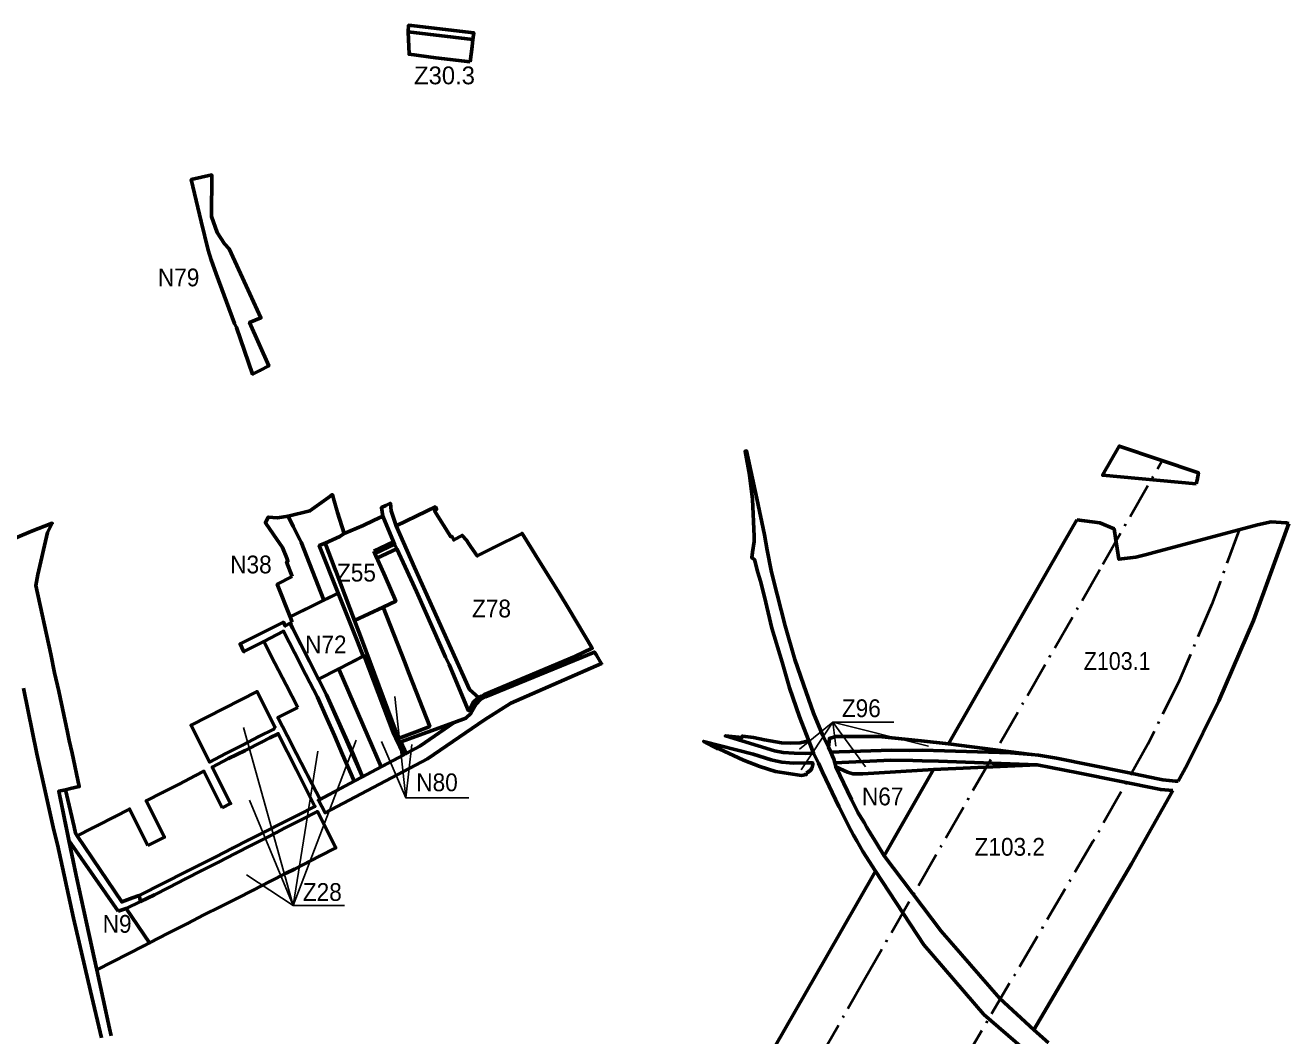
# Model space of a CAD drawing. Extents: x -650277 to -643420, y -1073980 to -1066720.
# Drawn here: x -648765 to -647061, y -1068122 to -1066758 of the extents above; entities that cross this region are included whole.
import ezdxf

# ---------------------------------------------------------------- set-up
doc = ezdxf.new("R2010")
doc.units = 0
doc.header["$LTSCALE"] = 9.6
doc.linetypes.add('DOT_DASHED', pattern=[7.7, 5, -1.2, 0.3, -1.2])
for name, color, linetype, lineweight in [('1', 7, 'Continuous', 60), ('15', 7, 'Continuous', 60), ('3', 7, 'Continuous', 60), ('40', 7, 'Continuous', 60), ('42', 7, 'Continuous', 60), ('45', 7, 'Continuous', 60), ('48', 7, 'Continuous', 60), ('60', 7, 'Continuous', 60), ('61', 7, 'Continuous', 60), ('62', 7, 'DOT_DASHED', 40), ('63', 7, 'Continuous', 25), ('7', 7, 'Continuous', 60), ('9', 7, 'Continuous', 60)]:
    doc.layers.add(name, color=color, linetype=linetype, lineweight=lineweight)

msp = doc.modelspace()

# ---------------------------------------------------------------- linework, layer by layer
at = {"layer": '1'}
msp.add_line((-648609.91, -1067940.58), (-648611.61, -1067932.63), dxfattribs=at)
for points in [[(-648397.98, -1067678.79), (-648424.69, -1067692.54), (-648412.19, -1067716.82), (-648399.58, -1067741.31), (-648387.04, -1067765.67), (-648384.25, -1067771.07), (-648367.811, -1067802.994), (-648321.623, -1067778.399), (-648326, -1067769), (-648337.32, -1067742.59), (-648348.55, -1067716.71), (-648359.6, -1067691.58), (-648371.34, -1067665.08), (-648386.91, -1067634.83), (-648402.02, -1067605.49), (-648417.12, -1067576.17), (-648443.83, -1067589.92), (-648428.7, -1067619.24), (-648413.57, -1067648.57)], [(-648342.697, -1067626.806), (-648369.949, -1067640.851), (-648359.213, -1067661.956), (-648310.511, -1067772.476), (-648285.254, -1067759.008), (-648296.891, -1067732.172), (-648342.023, -1067628.096)], [(-648519.63, -1067691.58), (-648541.86, -1067702.86), (-648516.73, -1067752.57), (-648494.84, -1067741.06), (-648472.5, -1067729.76), (-648450.23, -1067718.32), (-648430.17, -1067708.33), (-648428.67, -1067705.52), (-648452.72, -1067657.62)]]:
    msp.add_lwpolyline(points, close=True, dxfattribs=at)
for points in [[(-648399.64, -1067763.26), (-648424.14, -1067714.34), (-648435.34, -1067720.01), (-648446.58, -1067725.71), (-648468.97, -1067736.91), (-648480.06, -1067742.47), (-648491.14, -1067748.02), (-648513.23, -1067759.38), (-648488.49, -1067808.76), (-648499.7, -1067814.37)], [(-648611.61, -1067932.63), (-648547.09, -1067899.87), (-648530.81, -1067891.61), (-648508.22, -1067880.38), (-648486.09, -1067868.98), (-648463.91, -1067857.74), (-648441.47, -1067846.37), (-648419.44, -1067835.3), (-648397.04, -1067823.85), (-648374.84, -1067812.43), (-648399.64, -1067763.26)], [(-648499.7, -1067814.37), (-648524.44, -1067765.11), (-648535.61, -1067770.85), (-648557.84, -1067782.26), (-648580.14, -1067793.61), (-648602.3, -1067804.83), (-648577.78, -1067854.07), (-648600.14, -1067865.29)], [(-648600.14, -1067865.29), (-648624.76, -1067816.11), (-648645.11, -1067826.48), (-648668.085, -1067838.186), (-648675.26, -1067841.84), (-648695.27, -1067852.04), (-648664.41, -1067897.91)], [(-648572.5, -1067983.59), (-648546.76, -1067970.44), (-648524.72, -1067958.93), (-648502.59, -1067948), (-648480.12, -1067936.55), (-648457.87, -1067925.4), (-648435.55, -1067913.84), (-648413.41, -1067902.53), (-648402.29, -1067897.02), (-648391.08, -1067891.24), (-648368.78, -1067879.75), (-648346.57, -1067868.56), (-648371.27, -1067819.47), (-648393.35, -1067830.81), (-648415.69, -1067841.98), (-648426.65, -1067847.64), (-648437.89, -1067853.4), (-648460.33, -1067864.88), (-648482.5, -1067876.22), (-648504.92, -1067887.52), (-648527.33, -1067898.74), (-648549.44, -1067910.07), (-648571.88, -1067921.71), (-648591.04, -1067931.62), (-648609.91, -1067940.58)], [(-648664.41, -1067897.91), (-648635.249, -1067941.252), (-648620.658, -1067935.93), (-648611.61, -1067932.63)], [(-648609.91, -1067940.58), (-648629.22, -1067950.214), (-648597.93, -1067996.72), (-648572.5, -1067983.59)]]:
    msp.add_lwpolyline(points, dxfattribs=at)
at = {"layer": '15'}
msp.add_line((-648264.34, -1067464.83), (-648267.21, -1067458.61), dxfattribs=at)
for points in [[(-648161.58, -1066777.41), (-648160.51, -1066768.4), (-648248.43, -1066758.34), (-648248.77, -1066767.43)], [(-648362.585, -1067534.204), (-648343.41, -1067524.81), (-648369.01, -1067460.52), (-648361, -1067457.36), (-648341.15, -1067448.14), (-648335.38, -1067444.07), (-648344.41, -1067416.04), (-648349.67, -1067396.88), (-648351.06, -1067391.62), (-648352.16, -1067392.42), (-648353.35, -1067393.29), (-648381.48, -1067413.68), (-648410.92, -1067420.63), (-648409.61, -1067423.44), (-648404.29, -1067434.9), (-648394.92, -1067452.23), (-648393.17, -1067455.88)], [(-648237.81, -1067522.42), (-648204.88, -1067596.54), (-648198.39, -1067610.97), (-648193.8, -1067621), (-648189.03, -1067631.71), (-648167.48, -1067683.45), (-648164.79, -1067678.96), (-648163.11, -1067676.17), (-648160.68, -1067671.55), (-648153.98, -1067665.43), (-648166.173, -1067654.853), (-648240.51, -1067489.9), (-648265.197, -1067434.03), (-648265.197, -1067434.03), (-648272.022, -1067413.59), (-648273.008, -1067403.338), (-648279.24, -1067406.38), (-648285.08, -1067409.24), (-648283.21, -1067420.88), (-648268.67, -1067455.43), (-648267.21, -1067458.61), (-648294.04, -1067471.35), (-648291.172, -1067477.571), (-648264.34, -1067464.83), (-648253.1, -1067489.23)], [(-648359.6, -1067691.58), (-648348.55, -1067716.71), (-648337.32, -1067742.59), (-648326, -1067769), (-648321.623, -1067778.399), (-648310.511, -1067772.476), (-648323.178, -1067741.953), (-648359.213, -1067661.956), (-648405.054, -1067571.837), (-648408.002, -1067565.219), (-648414.73, -1067568.8), (-648417.19, -1067564.02), (-648475.78, -1067593.11), (-648473.34, -1067598.06), (-648470.57, -1067603.69), (-648470.47, -1067603.64), (-648443.83, -1067589.92), (-648417.12, -1067576.17), (-648402.02, -1067605.49), (-648386.91, -1067634.83), (-648371.34, -1067665.08)], [(-647988.235, -1067619.912), (-647995.04, -1067608.56), (-647997.68, -1067604.11), (-648144.83, -1067664.48), (-648151.6, -1067668.12), (-648157.2, -1067674.32), (-648161, -1067680.96), (-648162.69, -1067684), (-648164.09, -1067686.51), (-648171.21, -1067693.37), (-648187.139, -1067699.179), (-648233.264, -1067731.288), (-648251.711, -1067741.124), (-648258.96, -1067725.37), (-648262.632, -1067726.711), (-648255.016, -1067742.886), (-648319.983, -1067777.526), (-648370.113, -1067804.22), (-648360.993, -1067821.027), (-648222.872, -1067748.412), (-648146.127, -1067695.8), (-648110.36, -1067673.133), (-647988.052, -1067619.624)]]:
    msp.add_lwpolyline(points, close=True, dxfattribs=at)
for points in [[(-648793.71, -1067456.88), (-648757.97, -1067441.51), (-648728.95, -1067430.33), (-648735.59, -1067442.88), (-648748.53, -1067499.3), (-648751.29, -1067514.57), (-648731.06, -1067607.06), (-648725.8, -1067632.36), (-648720.1, -1067657.12), (-648708.26, -1067712.07), (-648706.08, -1067723.56), (-648702.33, -1067740.84), (-648692.53, -1067785.79), (-648704.614, -1067788.491), (-648710.961, -1067789.906), (-648720.34, -1067792), (-648696.93, -1067905.76), (-648672.31, -1068017.25), (-648668.92, -1068032.96), (-648651.89, -1068111.95), (-648649.74, -1068121.95)], [(-648267.21, -1067458.61), (-648294.04, -1067471.35), (-648291.172, -1067477.571), (-648264.34, -1067464.83)], [(-648662.71, -1068124.76), (-648677.61, -1068061.74), (-648700.16, -1067963.42), (-648722.09, -1067863.84), (-648727.05, -1067844.33), (-648738.7, -1067792.04), (-648749.97, -1067741.49), (-648767.84, -1067652.98)], [(-648710.961, -1067789.906), (-648720.34, -1067792), (-648706.687, -1067858.345), (-648640, -1067954)], [(-648695.27, -1067852.04), (-648697.7, -1067848.43), (-648699.621, -1067840.06), (-648699.593, -1067840.046), (-648710.96, -1067789.91)], [(-648611.61, -1067932.63), (-648620.658, -1067935.93), (-648635.249, -1067941.252), (-648664.41, -1067897.91), (-648695.27, -1067852.04)], [(-648640, -1067954), (-648629.22, -1067950.214), (-648609.91, -1067940.58), (-648611.61, -1067932.63)]]:
    msp.add_lwpolyline(points, dxfattribs=at)
at = {"layer": '3'}
msp.add_lwpolyline([(-648165.33, -1066807.74), (-648162.8, -1066786.8), (-648161.58, -1066777.41), (-648248.77, -1066767.43), (-648247.78, -1066797.53), (-648211.58, -1066802.18)], close=True, dxfattribs=at)
at = {"layer": '40'}
msp.add_lwpolyline([(-648405.27, -1067502.27), (-648425.5, -1067512.73), (-648408.26, -1067556.58), (-648362.585, -1067534.205), (-648393.17, -1067455.88), (-648394.92, -1067452.23), (-648404.29, -1067434.9), (-648410.92, -1067420.63), (-648425, -1067423.05), (-648437.75, -1067421.99), (-648441.48, -1067429.63), (-648430.4, -1067445.51), (-648418.3, -1067462.86), (-648412.46, -1067477.42), (-648411.25, -1067481.73), (-648412.89, -1067482.55)], close=True, dxfattribs=at)
at = {"layer": '42'}
msp.add_lwpolyline([(-647606.818, -1067879.061), (-647540.208, -1067762.876), (-647635.758, -1067768.38), (-647649.22, -1067768.38), (-647656.469, -1067766.309), (-647672.05, -1067758.98), (-647650.8, -1067803.28), (-647642.29, -1067820.76), (-647637.21, -1067829.29), (-647633.69, -1067834.31), (-647630.3, -1067841.02), (-647625.37, -1067848.86), (-647617.25, -1067861.95)], close=True, dxfattribs=at)
at = {"layer": '45'}
msp.add_lwpolyline([(-648405.41, -1067563.84), (-648408.002, -1067565.219), (-648369.949, -1067640.851), (-648342.697, -1067626.806), (-648328.54, -1067619.51), (-648309.522, -1067609.713), (-648317.43, -1067590), (-648343.41, -1067524.81), (-648408.26, -1067556.58)], close=True, dxfattribs=at)
at = {"layer": '48'}
for points in [[(-648528.01, -1067023.13), (-648518.72, -1067061.99), (-648514.86, -1067074.83), (-648507.88, -1067093.9), (-648483.31, -1067160.63), (-648480.57, -1067166.13), (-648458.73, -1067229.1), (-648449.03, -1067224.14), (-648437.02, -1067217.99), (-648462.97, -1067159.24), (-648447.66, -1067153.25), (-648467.56, -1067110.02), (-648490.23, -1067060.06), (-648496.87, -1067053.5), (-648506.78, -1067037.81), (-648514.38, -1067016.2), (-648513.842, -1066960.243), (-648541.52, -1066966.657)], [(-648342.023, -1067628.096), (-648296.891, -1067732.172), (-648285.254, -1067759.008), (-648255.016, -1067742.886), (-648265.614, -1067720.378), (-648269.27, -1067712.6), (-648308.43, -1067609.15), (-648328.54, -1067619.51), (-648342.697, -1067626.806)], [(-648258.96, -1067725.37), (-648251.711, -1067741.124), (-648233.264, -1067731.288), (-648187.139, -1067699.179)]]:
    msp.add_lwpolyline(points, close=True, dxfattribs=at)
for points in [[(-648265.08, -1067712.06), (-648261.25, -1067720.39), (-648235.78, -1067710.79), (-648219.86, -1067704.42), (-648247.53, -1067633.53), (-648254.04, -1067616.96), (-648282.863, -1067543.596), (-648321.36, -1067561.69)], [(-648321.361, -1067561.69), (-648311.95, -1067586.45), (-648265.08, -1067712.06)]]:
    msp.add_lwpolyline(points, dxfattribs=at)
at = {"layer": '60'}
for points in [[(-647606.818, -1067879.061), (-647617.25, -1067861.95), (-647625.37, -1067848.86), (-647630.3, -1067841.02), (-647633.69, -1067834.31), (-647637.21, -1067829.29), (-647642.29, -1067820.76), (-647650.8, -1067803.28), (-647672.05, -1067758.98), (-647673.47, -1067753.48), (-647673.47, -1067753.48), (-647674.67, -1067748.73), (-647676.47, -1067744.5), (-647678.66, -1067739.38), (-647681.91, -1067732.74), (-647690.09, -1067716.05), (-647702.04, -1067686.86), (-647715.92, -1067648.12), (-647727.37, -1067614.33), (-647740.49, -1067568.67), (-647751.41, -1067526.58), (-647756.55, -1067505.32), (-647759.16, -1067494.01), (-647764.89, -1067466.64), (-647768.5, -1067446.04), (-647778.78, -1067397.1), (-647792.52, -1067332.74), (-647794.54, -1067333.14), (-647788.77, -1067365.03), (-647784.55, -1067398.01), (-647782.39, -1067448.34), (-647782.5, -1067455.11), (-647784.36, -1067469.6), (-647785.64, -1067477.02), (-647781.85, -1067479.19), (-647777.55, -1067496.95), (-647773.96, -1067508.48), (-647768.5, -1067529.75), (-647758.25, -1067571.79), (-647744.61, -1067617.96), (-647734.63, -1067652.57), (-647721.05, -1067691.73), (-647708.71, -1067723.99), (-647702.21, -1067740.43), (-647699.89, -1067745.24), (-647697.85, -1067749.46), (-647695.71, -1067753.9), (-647690.19, -1067766.37), (-647668.13, -1067812.76), (-647651.94, -1067844.36), (-647648.33, -1067851.17), (-647643.83, -1067859.13), (-647635.77, -1067873.43), (-647618.773, -1067899.914)], [(-647783.54, -1067742.11), (-647850.45, -1067724.77), (-647838.18, -1067731.62), (-647832.56, -1067734.22), (-647829.49, -1067734.58), (-647796.87, -1067750.25), (-647774.54, -1067758.68), (-647753.53, -1067765.58), (-647718.54, -1067770.6), (-647712.01, -1067769.63), (-647712.26, -1067767.28)], [(-647712.26, -1067767.28), (-647711.773, -1067767.135), (-647711.286, -1067766.968), (-647710.799, -1067766.777), (-647710.315, -1067766.562), (-647709.834, -1067766.324), (-647709.359, -1067766.062), (-647708.892, -1067765.776), (-647708.433, -1067765.466), (-647707.985, -1067765.133), (-647707.55, -1067764.777), (-647707.128, -1067764.398), (-647706.723, -1067763.999), (-647706.335, -1067763.579), (-647705.966, -1067763.14), (-647705.617, -1067762.683), (-647705.29, -1067762.21), (-647704.985, -1067761.721), (-647704.704, -1067761.22), (-647704.447, -1067760.707), (-647704.216, -1067760.184), (-647704.01, -1067759.653), (-647703.83, -1067759.117), (-647703.675, -1067758.576), (-647703.547, -1067758.033), (-647703.445, -1067757.489), (-647703.368, -1067756.946), (-647703.315, -1067756.406), (-647703.287, -1067755.87), (-647703.282, -1067755.341), (-647703.3, -1067754.818), (-647703.34, -1067754.304), (-647703.4, -1067753.8), (-647711.09, -1067753.71), (-647728.98, -1067754.07), (-647734.69, -1067753.66), (-647744.74, -1067752.93), (-647757.74, -1067749.96), (-647759.13, -1067749.54), (-647783.54, -1067742.11)], [(-647405.026, -1068113.904), (-647451.024, -1068071.886), (-647530.038, -1067980.839), (-647606.818, -1067879.061)], [(-647618.773, -1067899.914), (-647553.628, -1067999.427), (-647472.338, -1068093.096), (-647419.713, -1068138.871)], [(-647385.13, -1068131.51), (-647405.026, -1068113.904)]]:
    msp.add_lwpolyline(points, dxfattribs=at)
for points in [[(-647754.88, -1067737.59), (-647743.12, -1067739.93), (-647728.29, -1067740.64), (-647713.15, -1067741), (-647702.21, -1067740.43), (-647708.71, -1067723.99), (-647720.45, -1067726.49), (-647732.71, -1067727.02), (-647745.41, -1067726.6), (-647768.53, -1067722.82), (-647783.13, -1067719.68), (-647798.17, -1067717.58), (-647798.5, -1067719.67), (-647821.02, -1067717.33)], [(-647596.91, -1067736.61), (-647572.33, -1067737.03), (-647555.58, -1067736.71), (-647525.685, -1067737.542), (-647436.72, -1067740.02), (-647408.2, -1067742.37), (-647520.145, -1067727.879), (-647557, -1067724), (-647614, -1067718), (-647643, -1067718), (-647672, -1067718), (-647680.804, -1067720.745), (-647681.91, -1067732.74), (-647678.66, -1067739.38), (-647678.66, -1067739.38), (-647667.76, -1067739.01), (-647638.75, -1067738.03)], [(-647540.208, -1067762.876), (-647400.63, -1067756.19), (-647533.597, -1067751.344), (-647555.67, -1067750.91), (-647568.36, -1067750.7), (-647597.83, -1067750.21), (-647673.47, -1067753.48), (-647672.05, -1067758.98), (-647672.05, -1067758.98), (-647656.469, -1067766.309), (-647649.22, -1067768.38), (-647635.758, -1067768.38)]]:
    msp.add_lwpolyline(points, close=True, dxfattribs=at)
at = {"layer": '61'}
msp.add_lwpolyline([(-647185.93, -1067377.38), (-647184.97, -1067372.22), (-647183.09, -1067362.16), (-647289.924, -1067326.309), (-647312.383, -1067365.484)], close=True, dxfattribs=at)
for points in [[(-647346.944, -1067425.768), (-647364.024, -1067455.561), (-647520.145, -1067727.879), (-647408.2, -1067742.37), (-647398.74, -1067743.15), (-647374.55, -1067747.34)], [(-647243.39, -1067469.81), (-647252.99, -1067472.35), (-647267.49, -1067476.23), (-647290.23, -1067478.89), (-647292.51, -1067464.56), (-647294.31, -1067453.26), (-647296.75, -1067437.91), (-647315.89, -1067429.71), (-647346.944, -1067425.768)], [(-647061.252, -1067430.908), (-647063.45, -1067430.19), (-647064.87, -1067429.73), (-647084.77, -1067428.64), (-647103.55, -1067432.54), (-647243.39, -1067469.81)], [(-647210.537, -1067778.594), (-647198.088, -1067756.5), (-647155.592, -1067670.17), (-647108.971, -1067561.55), (-647061.252, -1067430.908)], [(-647374.55, -1067747.34), (-647280.78, -1067766.44), (-647237.91, -1067775.18), (-647231.17, -1067776.55), (-647213.92, -1067778.26), (-647210.537, -1067778.594)], [(-647400.63, -1067756.19), (-647540.208, -1067762.876), (-647593.267, -1067855.425), (-647606.818, -1067879.061)], [(-647217.611, -1067791.149), (-647233.83, -1067789.69), (-647345.11, -1067767.28), (-647400.63, -1067756.19)], [(-647405.026, -1068113.904), (-647273.297, -1067889.981), (-647217.611, -1067791.149)], [(-647606.818, -1067879.061), (-647530.038, -1067980.839), (-647451.024, -1068071.886), (-647405.026, -1068113.904)], [(-647464.94, -1068215.752), (-647461.188, -1068209.373), (-647419.713, -1068138.871), (-647472.338, -1068093.096), (-647553.628, -1067999.427), (-647618.773, -1067899.914), (-647685.819, -1068016.861)], [(-647685.819, -1068016.861), (-647781.346, -1068183.485), (-647791.055, -1068200.507)]]:
    msp.add_lwpolyline(points, dxfattribs=at)
at = {"layer": '62'}
for points in [[(-647729.261, -1068213.27), (-647633.767, -1068046.703), (-647560.654, -1067919.174), (-647311.972, -1067485.403), (-647231.921, -1067345.773)], [(-647128.118, -1067439.088), (-647164.761, -1067539.408), (-647210.113, -1067645.071), (-647251.182, -1067728.502), (-647325.296, -1067860.04), (-647512.903, -1068178.95), (-647726.877, -1068542.68), (-647850.594, -1068756.441), (-647875.691, -1068807.609), (-647903.473, -1068876.174), (-647924.037, -1068940.973), (-647945.559, -1069039.601), (-647956.348, -1069145.994), (-647956.677, -1069214.977), (-647954.925, -1069248.93), (-647950.785, -1069292.731), (-647945.699, -1069329.377), (-647937.748, -1069374.683)]]:
    msp.add_lwpolyline(points, dxfattribs=at)
at = {"layer": '63'}
for p, q in [((-648404, -1067946), (-648471, -1067706)), ((-647676, -1067699), (-647672, -1067731)), ((-647676, -1067699), (-647632, -1067759)), ((-648404, -1067946), (-648319, -1067723)), ((-648404, -1067946), (-648371, -1067738)), ((-648404, -1067946), (-648463, -1067804))]:
    msp.add_line(p, q, dxfattribs=at)
for points in [[(-648267, -1067664), (-648252, -1067801), (-648285, -1067725)], [(-647594, -1067699), (-647676, -1067699), (-647721, -1067735)], [(-647547, -1067731), (-647676, -1067699), (-647719, -1067763)], [(-648244, -1067729), (-648252, -1067801), (-648167, -1067801)], [(-648335, -1067946), (-648404, -1067946), (-648467, -1067905)]]:
    msp.add_lwpolyline(points, dxfattribs=at)
at = {"layer": '7'}
msp.add_lwpolyline([(-648640, -1067954), (-648706.687, -1067858.345), (-648696.93, -1067905.76), (-648668.92, -1068032.96), (-648605.323, -1068000.463), (-648597.93, -1067996.72), (-648629.22, -1067950.214)], close=True, dxfattribs=at)
at = {"layer": '9'}
msp.add_lwpolyline([(-648153.98, -1067665.43), (-648149.933, -1067663.646), (-648146.21, -1067661.3), (-648023.96, -1067610.13), (-648000.63, -1067599.14), (-648031.77, -1067546.6), (-648045.04, -1067525.15), (-648076.32, -1067474.6), (-648081.31, -1067466.54), (-648095.28, -1067444.06), (-648133.56, -1067463.2), (-648150.46, -1067471.66), (-648155.85, -1067474.35), (-648164.24, -1067462.15), (-648166.97, -1067458.18), (-648170.38, -1067453.23), (-648175.94, -1067446.89), (-648187.44, -1067452.8), (-648190.23, -1067447.83), (-648191.46, -1067448.59), (-648213.34, -1067413.46), (-648210.48, -1067411.68), (-648211.08, -1067410.6), (-648212.32, -1067408.39), (-648224.19, -1067414.14), (-648265.197, -1067434.03), (-648240.51, -1067489.9), (-648240.51, -1067489.9), (-648166.173, -1067654.853)], close=True, dxfattribs=at)
for points in [[(-648295.409, -1067468.129), (-648268.67, -1067455.43), (-648283.21, -1067420.88), (-648295.66, -1067426.76), (-648309.57, -1067433.34), (-648335.38, -1067444.07), (-648341.15, -1067448.14), (-648361, -1067457.36), (-648347.51, -1067492.87), (-648346.27, -1067496.14)], [(-648346.27, -1067496.14), (-648334.09, -1067528.2), (-648321.36, -1067561.69), (-648282.863, -1067543.596), (-648265.757, -1067535.555), (-648279.86, -1067502.11), (-648294.04, -1067471.35), (-648295.409, -1067468.129)]]:
    msp.add_lwpolyline(points, dxfattribs=at)

# ---------------------------------------------------------------- texts
at = {"layer": '63'}
msp.add_text('Z30.3', height=24, dxfattribs=at).set_placement((-648241, -1066838))
for s, width, p in [('N79', 0.95, (-648586.544, -1067110.648)), ('N38', 0.95, (-648489, -1067498)), ('Z55', 0.95, (-648345, -1067509)), ('Z78', 0.95, (-648162.836, -1067557.421)), ('N72', 0.95, (-648388, -1067606)), ('Z103.1', 0.9, (-647337.666, -1067628.26)), ('Z96', 0.95, (-647664, -1067692)), ('N80', 0.95, (-648238, -1067792)), ('N67', 0.95, (-647636.885, -1067811.038)), ('Z103.2', 0.95, (-647485, -1067879)), ('Z28', 0.95, (-648391, -1067940)), ('N9', 0.95, (-648661, -1067983))]:
    msp.add_text(s, height=24, dxfattribs=dict(at, width=width)).set_placement(p)

doc.saveas('drawing.dxf')
